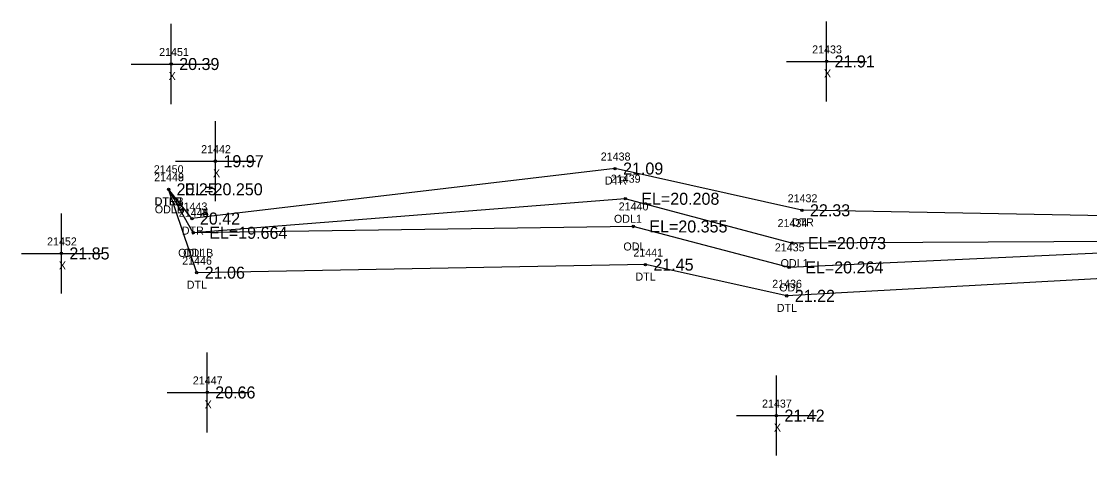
# Model space of a CAD drawing. Extents: x 2655177 to 2656219, y 761780 to 764748.
# Drawn here: x 2655215.5 to 2655348.9, y 762020.4 to 762074.6 of the extents above; entities that cross this region are included whole.
import ezdxf

# ---------------------------------------------------------------- set-up
doc = ezdxf.new("R2010")
doc.units = 0
for name, color, linetype in [('RD_EX_H2O', 7, 'Continuous'), ('RD_EX_H2O_txCode', 7, 'Continuous'), ('RD_EX_Misc', 7, 'Continuous'), ('RD_EX_Misc_txCode', 7, 'Continuous'), ('RD_EX_TX_H2O_ELEV', 7, 'Continuous'), ('RD_EX_TX_Misc_ELEV', 7, 'Continuous'), ('RD_SMD_Locator', 7, 'Continuous')]:
    doc.layers.add(name, color=color, linetype=linetype)

msp = doc.modelspace()

# ---------------------------------------------------------------- linework, layer by layer
at = {"layer": 'RD_EX_H2O'}
for points in [[(2655388.95, 762049.63), (2655313, 762051.05), (2655289.65, 762056.26), (2655236.79, 762050.02), (2655233.87, 762053.67)], [(2655386.96, 762044.53), (2655311.1, 762040.37), (2655293.44, 762044.27), (2655237.39, 762043.26), (2655233.87, 762053.67)], [(2655385.37, 762047.33), (2655311.4, 762043.92), (2655291.93, 762049.03), (2655236.95, 762048.24), (2655233.87, 762053.67)], [(2655385.37, 762047.33), (2655311.74, 762046.95), (2655290.92, 762052.49), (2655236.95, 762048.24)]]:
    msp.add_lwpolyline(points, dxfattribs=at)
at = {"layer": 'RD_EX_Misc'}
for p, q in [((2655234.2, 762064.31), (2655234.2, 762074.31)), ((2655316.07, 762064.63), (2655316.07, 762074.63)), ((2655311.07, 762069.63), (2655321.07, 762069.63)), ((2655229.2, 762069.31), (2655239.2, 762069.31)), ((2655239.73, 762052.18), (2655239.73, 762062.18)), ((2655234.73, 762057.18), (2655244.73, 762057.18)), ((2655220.48, 762040.66), (2655220.48, 762050.66)), ((2655215.48, 762045.66), (2655225.48, 762045.66)), ((2655238.7, 762023.31), (2655238.7, 762033.31)), ((2655309.81, 762020.42), (2655309.81, 762030.42)), ((2655233.7, 762028.31), (2655243.7, 762028.31)), ((2655304.81, 762025.42), (2655314.81, 762025.42))]:
    msp.add_line(p, q, dxfattribs=at)
at = {"layer": 'RD_SMD_Locator'}
for centre in [(2655316.07, 762069.63), (2655234.2, 762069.31), (2655239.73, 762057.18), (2655289.65, 762056.26), (2655233.87, 762053.67), (2655233.87, 762053.67), (2655233.87, 762053.67), (2655290.92, 762052.49), (2655313, 762051.05), (2655236.79, 762050.02), (2655236.95, 762048.24), (2655236.95, 762048.24), (2655291.93, 762049.03), (2655311.74, 762046.95), (2655220.48, 762045.66), (2655293.44, 762044.27), (2655237.39, 762043.26), (2655311.4, 762043.92), (2655311.1, 762040.37), (2655238.7, 762028.31), (2655309.81, 762025.42)]:
    msp.add_circle(centre, 0.15, dxfattribs=at)

# ---------------------------------------------------------------- texts
at = {"layer": 'RD_EX_H2O_txCode'}
for s, p in [('21438', (2655287.86, 762057.26)), ('21450', (2655232.03, 762055.67)), ('21448', (2655232.07, 762054.67)), ('21449', (2655232.07, 762054.67)), ('DTR', (2655288.38, 762054.26)), ('21439', (2655289.12, 762054.49)), ('DTRB', (2655232.13, 762051.67)), ('DTLB', (2655232.15, 762051.67)), ('21432', (2655311.21, 762052.05)), ('ODLB', (2655232.15, 762050.67)), ('21443', (2655235, 762051.02)), ('21444', (2655235.15, 762050.24)), ('21445', (2655235.15, 762050.24)), ('21440', (2655290.1, 762051.03)), ('ODL1', (2655289.51, 762049.49)), ('21434', (2655309.95, 762048.95)), ('DTR', (2655311.73, 762049.05)), ('DTR', (2655235.52, 762048.02)), ('ODL', (2655290.69, 762046.03)), ('21435', (2655309.61, 762045.92)), ('ODL1B', (2655235.07, 762045.24)), ('ODL', (2655235.7, 762045.24)), ('21441', (2655291.93, 762045.27)), ('21446', (2655235.57, 762044.26)), ('ODL1', (2655310.33, 762043.95)), ('DTL', (2655292.19, 762042.27)), ('DTL', (2655236.14, 762041.26)), ('21436', (2655309.28, 762041.37)), ('ODL', (2655310.16, 762040.92)), ('DTL', (2655309.85, 762038.37))]:
    msp.add_text(s, height=1, dxfattribs=at).set_placement(p)
at = {"layer": 'RD_EX_Misc_txCode'}
for s, p in [('21451', (2655232.69, 762070.31)), ('21433', (2655314.27, 762070.63)), ('X', (2655233.88, 762067.31)), ('X', (2655315.75, 762067.63)), ('21442', (2655237.94, 762058.18)), ('X', (2655239.42, 762055.18)), ('21452', (2655218.69, 762046.66)), ('X', (2655220.17, 762043.66)), ('21447', (2655236.9, 762029.31)), ('X', (2655238.38, 762026.31)), ('21437', (2655308.01, 762026.42)), ('X', (2655309.49, 762023.42))]:
    msp.add_text(s, height=1, dxfattribs=at).set_placement(p)
at = {"layer": 'RD_EX_TX_H2O_ELEV'}
for s, p in [('21.09', (2655290.65, 762055.51)), ('20.25', (2655234.87, 762052.92)), ('20.25', (2655234.87, 762052.92)), ('EL=20.250', (2655235.87, 762052.92)), ('EL=20.208', (2655292.92, 762051.74)), ('22.33', (2655314, 762050.3)), ('20.42', (2655237.79, 762049.27)), ('EL=20.355', (2655293.93, 762048.28)), ('EL=19.664', (2655238.95, 762047.49)), ('EL=19.664', (2655238.95, 762047.49)), ('EL=20.073', (2655313.74, 762046.2)), ('21.45', (2655294.44, 762043.52)), ('EL=20.264', (2655313.4, 762043.17)), ('21.06', (2655238.39, 762042.51)), ('21.22', (2655312.1, 762039.62))]:
    msp.add_text(s, height=1.5, dxfattribs=at).set_placement(p)
at = {"layer": 'RD_EX_TX_Misc_ELEV'}
for s, p in [('20.39', (2655235.2, 762068.56)), ('21.91', (2655317.07, 762068.88)), ('19.97', (2655240.73, 762056.43)), ('21.85', (2655221.48, 762044.91)), ('20.66', (2655239.7, 762027.56)), ('21.42', (2655310.81, 762024.67))]:
    msp.add_text(s, height=1.5, dxfattribs=at).set_placement(p)

doc.saveas('drawing.dxf')
